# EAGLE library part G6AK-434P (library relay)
RELAY 4 x switch, dual coil latching, 0.3 A/125 V AC, 1 A/30 V DC, Omron
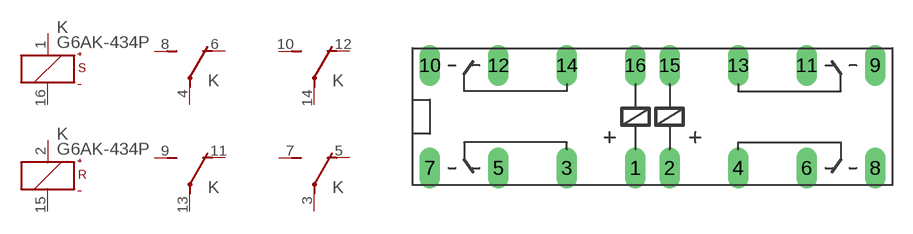
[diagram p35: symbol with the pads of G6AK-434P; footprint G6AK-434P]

Designator prefix K; gates -S=K+-S -R=K+-R -1=U -2=U -3=U -4=U

## G6AK-434P (OC_FARNELL: unknown; OC_NEWARK: unknown)  [G6AK-434P]
1  -S:+  pas
2  -R:+  pas
3  -4:P  pas
4  -1:P  pas
5  -4:O  pas
6  -1:O  pas
7  -4:S  pas
8  -1:S  pas
9  -2:S  pas
10  -3:S  pas
11  -2:O  pas
12  -3:O  pas
13  -2:P  pas
14  -3:P  pas
15  -R:-  pas
16  -S:-  pas

## Footprint G6AK-434P (pad centres in mm)
RELAY 4 x switch, dual coil latching, 0.3 A/125 V AC, 1 A/30 V DC, Omron
drill 1.016 long: 1 -1.27,-3.81; 2 1.27,-3.81; 3 -6.35,-3.81; 4 6.35,-3.81; 5 -11.43,-3.81; 6 11.43,-3.81; 7 -16.51,-3.81; 8 16.51,-3.81; 9 16.51,3.81; 10 -16.51,3.81; 11 11.43,3.81; 12 -11.43,3.81; 13 6.35,3.81; 14 -6.35,3.81; 15 1.27,3.81; 16 -1.27,3.81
